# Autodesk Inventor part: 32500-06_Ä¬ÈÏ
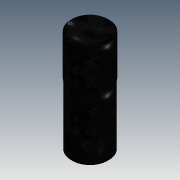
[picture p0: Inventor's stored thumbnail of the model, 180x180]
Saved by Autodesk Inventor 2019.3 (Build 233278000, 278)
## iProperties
Created: 2010-06
Part Number: 32500-06_Ä¬ÈÏ
Material: Ogólny
Document SubType Name: Modeling
Designer: CADENGINEERING4
Density: 1 g/cm^3
Appearance: Czarny
Author: CADENGINEERING4
Revision Number: ÈÎºÎ
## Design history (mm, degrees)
feature "NONE"
node "Bryła1"
